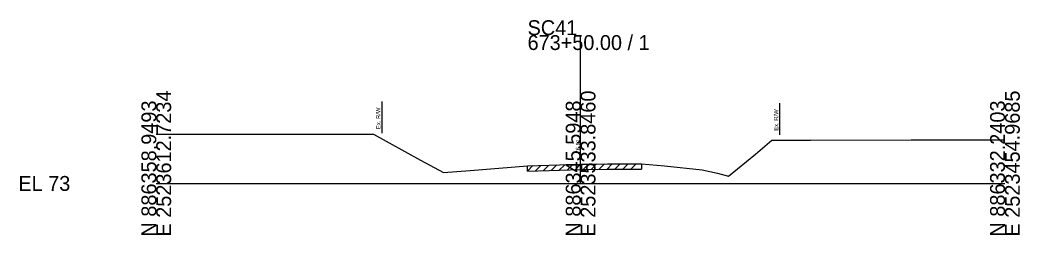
# Model space of a CAD drawing. Extents: x -26 to 183, y -10 to 24021.
# Drawn here: x -25.7 to 162.8, y 5990.3 to 6030.7 of the extents above; entities that cross this region are included whole.
import ezdxf

# ---------------------------------------------------------------- set-up
doc = ezdxf.new("R2010")
doc.units = 0
for name, color, linetype in [('RD_GPK_XS_Cell', 7, 'Continuous'), ('RD_XS_ExGround', 7, 'Continuous'), ('RD_XS_ExPaveRet', 7, 'Continuous'), ('RD_XS_ExRW', 7, 'Continuous'), ('RD_XS_TX_Elev_EX', 7, 'Continuous')]:
    doc.layers.add(name, color=color, linetype=linetype)

msp = doc.modelspace()

# ---------------------------------------------------------------- linework, layer by layer
at = {"layer": 'RD_GPK_XS_Cell'}
for p, q in [((80, 6000), (80, 6027.91)), ((0, 6000), (80, 6000)), ((80, 6000), (160, 6000))]:
    msp.add_line(p, q, dxfattribs=at)
at = {"layer": 'RD_XS_ExGround'}
for p, q in [((0, 6009.26), (2.87, 6009.26)), ((2.87, 6009.26), (22.27, 6009.28)), ((22.27, 6009.28), (34.81, 6009.29)), ((34.81, 6009.29), (40.96, 6009.3)), ((40.96, 6009.3), (49.83, 6004.36)), ((112.97, 6005.53), (116.06, 6008.12)), ((116.06, 6008.12), (123.33, 6008.16)), ((123.33, 6008.16), (142.29, 6008.19)), ((142.29, 6008.19), (160, 6008.23)), ((107.91, 6001.4), (112.97, 6005.53)), ((49.83, 6004.36), (54.18, 6002.05)), ((59.18, 6002.43), (69.98, 6003.33)), ((69.98, 6003.33), (74.09, 6003.44)), ((74.09, 6003.44), (80, 6003.61)), ((80, 6003.61), (81.49, 6003.65)), ((81.49, 6003.65), (85.08, 6003.67)), ((85.08, 6003.67), (91.49, 6003.71)), ((91.49, 6003.71), (95.79, 6003.29)), ((95.79, 6003.29), (102.92, 6002.59)), ((54.18, 6002.05), (59.18, 6002.43)), ((102.92, 6002.59), (105.8, 6001.91)), ((105.8, 6001.91), (107.91, 6001.4))]:
    msp.add_line(p, q, dxfattribs=at)
at = {"layer": 'RD_XS_ExPaveRet'}
for p, q in [((69.98, 6002.33), (71.01, 6003.36)), ((69.98, 6002.33), (69.98, 6003.33)), ((71.48, 6002.37), (72.51, 6003.4)), ((72.98, 6002.41), (74.01, 6003.44)), ((74.48, 6002.45), (75.51, 6003.48)), ((75.98, 6002.49), (77.01, 6003.52)), ((77.48, 6002.53), (78.51, 6003.56)), ((78.98, 6002.58), (80.01, 6003.61)), ((80.48, 6002.62), (81.51, 6003.65)), ((81.98, 6002.65), (82.98, 6003.66)), ((83.48, 6002.66), (84.48, 6003.67)), ((84.98, 6002.67), (85.98, 6003.68)), ((86.48, 6002.68), (87.48, 6003.69)), ((87.98, 6002.69), (88.98, 6003.7)), ((89.48, 6002.7), (90.48, 6003.71)), ((91.49, 6003.71), (91.49, 6002.71)), ((69.98, 6002.33), (74.09, 6002.44)), ((74.09, 6002.44), (80, 6002.61)), ((80, 6002.61), (81.49, 6002.65)), ((81.49, 6002.65), (85.08, 6002.67)), ((85.08, 6002.67), (91.49, 6002.71))]:
    msp.add_line(p, q, dxfattribs=at)
at = {"layer": 'RD_XS_ExRW'}
for p, q in [((42.5, 6015.44), (42.5, 6009.44)), ((117.5, 6015.13), (117.5, 6009.13))]:
    msp.add_line(p, q, dxfattribs=at)

# ---------------------------------------------------------------- texts
at = {"layer": 'RD_GPK_XS_Cell'}
for s, p in [('SC41', (70, 6027.91)), ('673+50.00 / 1', (70, 6025.11)), ('EL 73', (-26, 5998.6))]:
    msp.add_text(s, height=2.8, dxfattribs=at).set_placement(p)
for s, p in [('E 2523612.7234', (2.8, 5990)), ('E 2523533.8460', (82.8, 5990)), ('E 2523454.9685', (162.8, 5990)), ('N 886358.9493', (0, 5990)), ('N 886345.5948', (80, 5990)), ('N 886332.2403', (160, 5990))]:
    msp.add_text(s, height=2.8, rotation=90, dxfattribs=at).set_placement(p)
at = {"layer": 'RD_XS_ExRW'}
for p in [(42.25, 6010.23), (117.25, 6009.91)]:
    msp.add_text('Ex. R/W ', height=0.8, rotation=90, dxfattribs=at).set_placement(p)
at = {"layer": 'RD_XS_TX_Elev_EX'}
msp.add_text('76.61', height=0.8, rotation=90, dxfattribs=at).set_placement((79.9, 6005.61))

doc.saveas('drawing.dxf')
